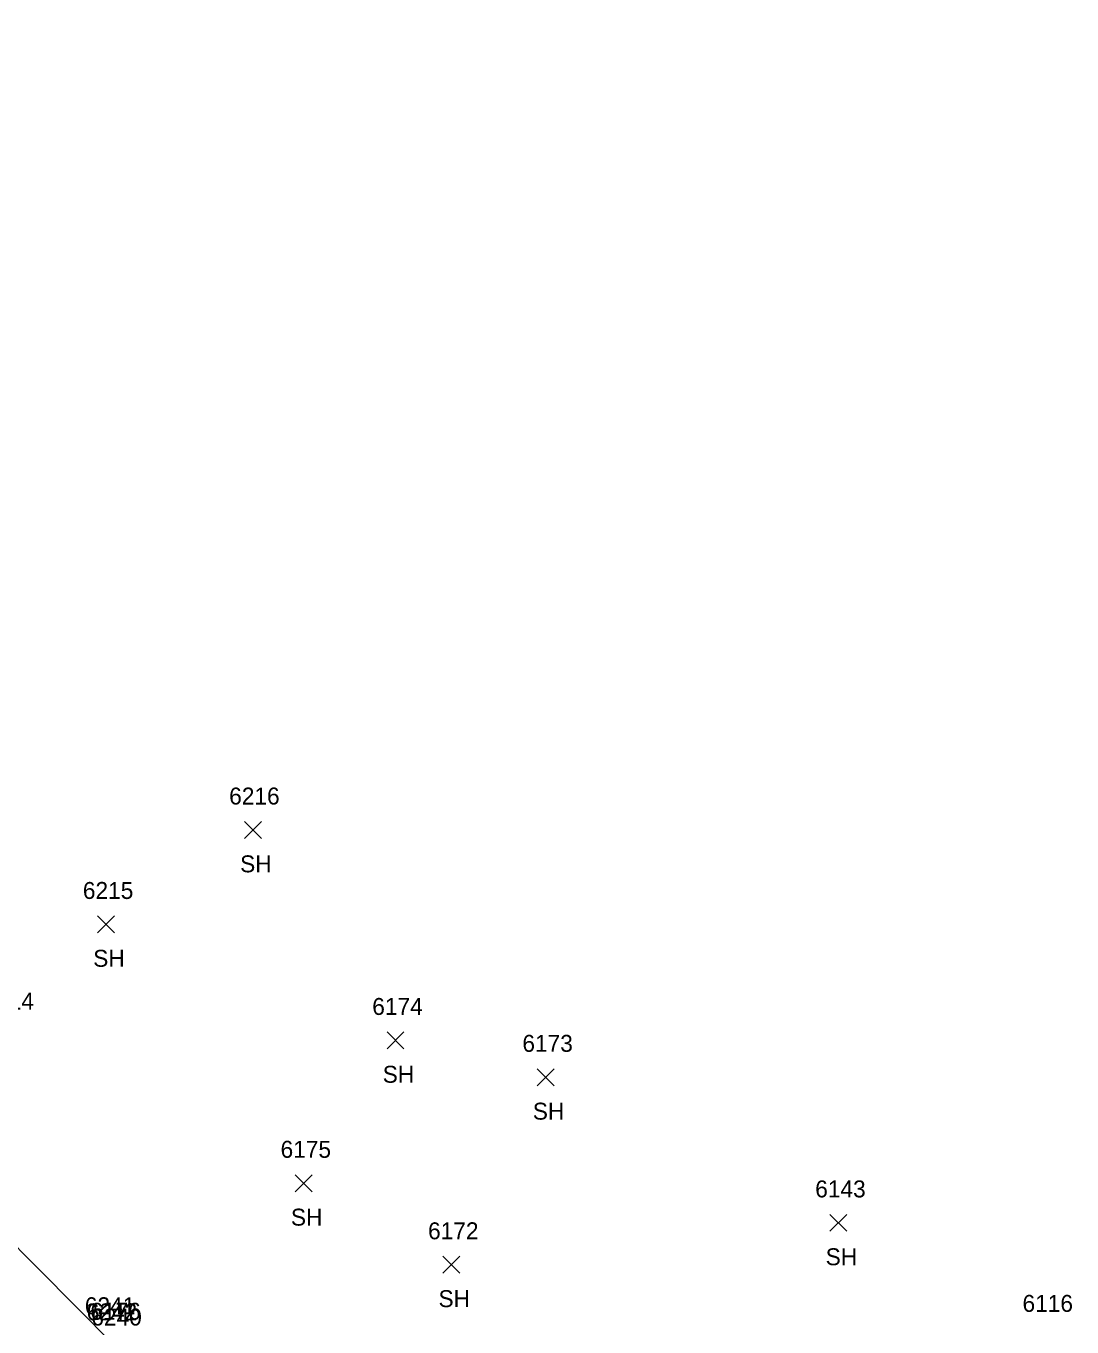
# Model space of a CAD drawing. Extents: x 1618146 to 1620418, y 640749 to 641927.
# Drawn here: x 1619881.9 to 1620005.2, y 641450.1 to 641603.6 of the extents above; entities that cross this region are included whole.
import ezdxf

# ---------------------------------------------------------------- set-up
doc = ezdxf.new("R2010")
doc.units = 0
for name, color, linetype in [('D_I', 7, 'Continuous'), ('L_A', 7, 'Continuous'), ('L_I', 7, 'Continuous'), ('L_TIC', 7, 'Continuous'), ('LELB', 7, 'Continuous')]:
    doc.layers.add(name, color=color, linetype=linetype)

msp = doc.modelspace()

# ---------------------------------------------------------------- linework, layer by layer
at = {"layer": 'L_TIC'}
for points in [[(1619907.65, 641507.76), (1619909.65, 641509.76)], [(1619909.65, 641507.76), (1619907.65, 641509.76)], [(1619890.34, 641496.62), (1619892.34, 641498.62)], [(1619892.34, 641496.62), (1619890.34, 641498.62)], [(1619924.46, 641482.94), (1619926.46, 641484.94)], [(1619926.46, 641482.94), (1619924.46, 641484.94)], [(1619942.16, 641478.59), (1619944.16, 641480.59)], [(1619944.16, 641478.59), (1619942.16, 641480.59)], [(1619913.65, 641466.09), (1619915.65, 641468.09)], [(1619915.65, 641466.09), (1619913.65, 641468.09)], [(1619976.69, 641461.42), (1619978.69, 641463.42)], [(1619978.69, 641461.42), (1619976.69, 641463.42)], [(1619931.04, 641456.48), (1619933.04, 641458.48)], [(1619933.04, 641456.48), (1619931.04, 641458.48)]]:
    msp.add_lwpolyline(points, dxfattribs=at)
at = {"layer": 'LELB'}
msp.add_lwpolyline([(1620001.62, 641448.92), (1619993.41, 641422.16), (1619984.98, 641398.34), (1619977.06, 641384.68), (1619950.18, 641400.93), (1619916.84, 641428.62), (1619892.28, 641447.99), (1619869.79, 641470.62), (1619837.68, 641499.78), (1619817.4, 641519.66), (1619791.65, 641544.13), (1619796.59, 641561.17), (1619804.29, 641584.54), (1619783.72, 641603.58)], dxfattribs=at)

# ---------------------------------------------------------------- texts
at = {"layer": 'D_I'}
for s, p in [('6241', (1619888.83, 641451.64)), ('6242', (1619889.05, 641450.92)), ('6176', (1619889.48, 641450.99)), ('6240', (1619889.6, 641450.31))]:
    msp.add_text(s, height=2, dxfattribs=at).set_placement(p)
at = {"layer": 'L_A'}
for p in [(1619907.14, 641503.76), (1619889.82, 641492.62), (1619923.95, 641478.94), (1619941.65, 641474.59), (1619913.13, 641462.09), (1619976.18, 641457.42), (1619930.53, 641452.48)]:
    msp.add_text('SH', height=2, dxfattribs=at).set_placement(p)
at = {"layer": 'L_I'}
for s, p in [('6216', (1619905.85, 641511.76)), ('6215', (1619888.6, 641500.62)), ('6214', (1619876.88, 641487.58)), ('6174', (1619922.72, 641486.94)), ('6173', (1619940.42, 641482.59)), ('6175', (1619911.91, 641470.09)), ('6143', (1619974.95, 641465.42)), ('6172', (1619929.3, 641460.48)), ('6116', (1619999.39, 641451.92)), ('6176', (1619889.48, 641450.99))]:
    msp.add_text(s, height=2, dxfattribs=at).set_placement(p)

doc.saveas('drawing.dxf')
